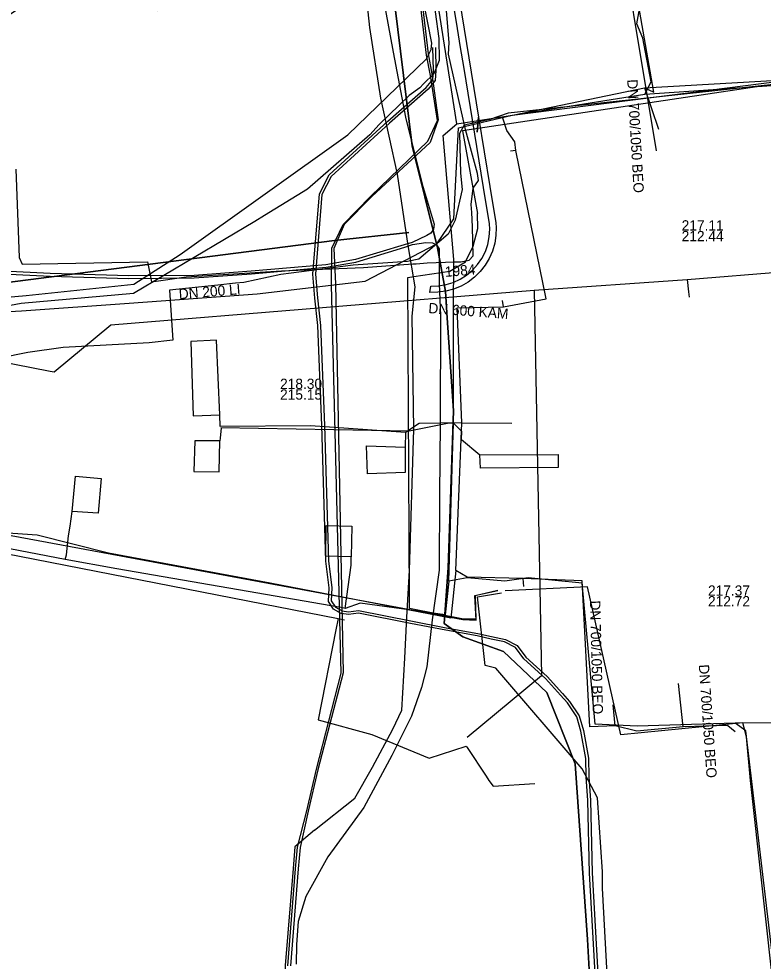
# Model space of a CAD drawing. Extents: x -599951 to -598963, y -1164095 to -1162939.
# Drawn here: x -599282.6 to -599224.6, y -1163195.6 to -1163122.3 of the extents above; entities that cross this region are included whole.
import ezdxf

# ---------------------------------------------------------------- set-up
doc = ezdxf.new("R2010")
doc.units = 0
for name, color, linetype in [('Level 3', 7, 'Continuous'), ('Vrstva 12', 7, 'Continuous'), ('Vrstva 13', 7, 'Continuous'), ('Vrstva 15', 7, 'Continuous'), ('Vrstva 19', 7, 'Continuous'), ('Vrstva 32', 7, 'Continuous'), ('Vrstva 42', 7, 'Continuous'), ('Vrstva 44', 7, 'Continuous'), ('Vrstva 55', 7, 'Continuous'), ('Vrstva 58', 7, 'Continuous')]:
    doc.layers.add(name, color=color, linetype=linetype)

msp = doc.modelspace()

# ---------------------------------------------------------------- linework, layer by layer
at = {"layer": 'Level 3'}
msp.add_lwpolyline([(-599249.571, -1163112.7), (-599246.751, -1163129.952), (-599246.869, -1163131.103), (-599246.751, -1163129.952), (-599245.87, -1163135.341), (-599245.405, -1163138.167), (-599245.38, -1163138.516), (-599245.397, -1163139.141), (-599245.494, -1163139.759), (-599245.669, -1163140.359), (-599245.92, -1163140.933), (-599246.241, -1163141.47), (-599246.628, -1163141.961), (-599247.074, -1163142.399), (-599247.573, -1163142.777), (-599248.116, -1163143.088), (-599248.694, -1163143.327), (-599249.298, -1163143.49), (-599249.917, -1163143.575), (-599250.543, -1163143.581), (-599250.464, -1163143.084), (-599249.872, -1163143.07), (-599249.286, -1163142.976), (-599248.719, -1163142.805), (-599248.18, -1163142.558), (-599247.679, -1163142.241), (-599247.225, -1163141.86), (-599246.827, -1163141.421), (-599246.491, -1163140.933), (-599246.224, -1163140.404), (-599246.03, -1163139.844), (-599245.914, -1163139.262), (-599245.877, -1163138.671), (-599245.901, -1163138.248), (-599245.898, -1163138.248), (-599246.363, -1163135.422), (-599247.904, -1163125.994), (-599248.146, -1163124.512), (-599248.227, -1163124.018), (-599248.389, -1163123.03), (-599250.067, -1163112.766)], dxfattribs=at)
at = {"layer": 'Vrstva 13'}
for p, q in [((-599230.497, -1163142.575), (-599230.399, -1163143.53)), ((-599230.399, -1163143.53), (-599230.35, -1163143.945)), ((-599286.249, -1163148.514), (-599280.123, -1163149.708))]:
    msp.add_line(p, q, dxfattribs=at)
for points in [[(-599280.123, -1163149.708), (-599279.79, -1163149.777), (-599275.388, -1163146.114), (-599242.43, -1163143.42), (-599230.497, -1163142.575), (-599222.86, -1163141.962)], [(-599242.43, -1163143.42), (-599241.851, -1163173.435), (-599247.646, -1163178.245)]]:
    msp.add_lwpolyline(points, dxfattribs=at)
at = {"layer": 'Vrstva 19'}
for points in [[(-599283.03, -1163098.11), (-599283, -1163099.78), (-599282.98, -1163100.28), (-599282.759, -1163104.88), (-599282.75, -1163105.07), (-599281.86, -1163119.78), (-599282.17, -1163121.21), (-599283.38, -1163122.06), (-599284.63, -1163122.58), (-599291.87, -1163126.57), (-599293.2, -1163127.71), (-599294.09, -1163129.72), (-599294.97, -1163134.86), (-599295.61, -1163139.68), (-599296.53, -1163145.79), (-599296.83, -1163147.64), (-599298.55, -1163147.69), (-599298.47, -1163148.23), (-599298.58, -1163159.15), (-599298.84, -1163160.93), (-599298.41, -1163161.06), (-599297.782, -1163161.141), (-599257.68, -1163168.97), (-599257.189, -1163169.066)], [(-599257.68, -1163168.97), (-599257.856, -1163169.853), (-599259.25, -1163176.86), (-599255.07, -1163177.99), (-599250.6, -1163179.85), (-599247.73, -1163178.9), (-599247.64, -1163179.02), (-599246.169, -1163181.239), (-599245.95, -1163181.57), (-599245.61, -1163182.03), (-599242.36, -1163181.82)]]:
    msp.add_lwpolyline(points, dxfattribs=at)
at = {"layer": 'Vrstva 32'}
msp.add_line((-599230.82, -1163177.41), (-599231.188, -1163174.019), dxfattribs=at)
for points in [[(-599233.09, -1163128), (-599234.85, -1163118.03)], [(-599252.44, -1163154.48), (-599259.85, -1163153.98), (-599266.88, -1163154.01), (-599266.91, -1163153.12), (-599267.17, -1163147.3), (-599269.17, -1163147.4), (-599268.97, -1163153.2), (-599266.91, -1163153.12)], [(-599248.05, -1163153.74), (-599251.39, -1163153.8), (-599252.44, -1163154.48), (-599252.46, -1163155.64), (-599252.47, -1163157.61), (-599255.39, -1163157.71), (-599255.47, -1163155.53), (-599252.46, -1163155.64)], [(-599248.51, -1163165.23), (-599248.91, -1163168.93), (-599262.99, -1163166.23), (-599275.57, -1163163.89), (-599281.12, -1163162.48), (-599284.95, -1163162.23), (-599289.25, -1163161.14), (-599288.98, -1163159.59), (-599288.46, -1163154.45), (-599290.46, -1163154.22), (-599290.93, -1163159.09), (-599288.98, -1163159.59)]]:
    msp.add_lwpolyline(points, dxfattribs=at)
at = {"layer": 'Vrstva 42'}
for p, q in [((-599244.136, -1163129.788), (-599217.775, -1163126.435)), ((-599244.136, -1163129.788), (-599217.775, -1163126.435)), ((-599233.82, -1163127.66), (-599232.74, -1163130.88)), ((-599248.304, -1163130.763), (-599244.136, -1163129.788)), ((-599248.304, -1163130.763), (-599244.136, -1163129.788)), ((-599248.665, -1163137.857), (-599248.304, -1163130.763)), ((-599248.665, -1163137.857), (-599248.304, -1163130.763)), ((-599243.86, -1163132.53), (-599244.26, -1163132.58)), ((-599249.995, -1163139.796), (-599248.665, -1163137.857)), ((-599249.995, -1163139.796), (-599248.665, -1163137.857)), ((-599255.591, -1163142.7), (-599249.995, -1163139.796)), ((-599255.591, -1163142.7), (-599249.995, -1163139.796)), ((-599263.99, -1163143.703), (-599255.591, -1163142.7)), ((-599263.99, -1163143.703), (-599255.591, -1163142.7)), ((-599273.951, -1163144.417), (-599263.99, -1163143.703)), ((-599273.951, -1163144.417), (-599263.99, -1163143.703)), ((-599244.8, -1163144.71), (-599244.9, -1163144.2)), ((-599282.345, -1163145.018), (-599273.951, -1163144.417)), ((-599282.345, -1163145.018), (-599273.951, -1163144.417)), ((-599291.448, -1163145.455), (-599282.345, -1163145.018)), ((-599291.448, -1163145.455), (-599282.345, -1163145.018)), ((-599248.05, -1163153.74), (-599244.16, -1163153.77)), ((-599236.11, -1163177.32), (-599236.27, -1163175.68)), ((-599230.82, -1163177.41), (-599230.82, -1163177.41)), ((-599227.33, -1163177.3), (-599226.77, -1163177.77))]:
    msp.add_line(p, q, dxfattribs=at)
for points in [[(-599233.795, -1163128.148), (-599233.302, -1163127.176), (-599233.948, -1163123.785), (-599234.414, -1163122.681), (-599234.221, -1163121.532), (-599236.225, -1163106.079), (-599238.167, -1163087.208), (-599239.204, -1163068.612), (-599240.268, -1163050.177), (-599241.368, -1163030.944), (-599242.272, -1163013.415), (-599243.328, -1162996.385), (-599244.094, -1162980.53), (-599243.642, -1162980.475)], [(-599248.449, -1163130.464), (-599249.959, -1163120.858), (-599250.954, -1163118.557), (-599251.444, -1163116.855), (-599251.095, -1163114.116), (-599252.405, -1163100.665), (-599252.226, -1163100.394)], [(-599236.04, -1163234.14), (-599238.28, -1163193.96), (-599239.23, -1163180.29), (-599241.44, -1163174.74), (-599244.81, -1163171.53), (-599247.98, -1163170.4), (-599249.42, -1163169.35), (-599249.11, -1163165.02), (-599248.71, -1163152.8), (-599249.2, -1163145.57), (-599249.33, -1163143.51), (-599249.96, -1163140.12), (-599251.93, -1163132.17), (-599253.26, -1163121.21), (-599253.403, -1163121.072), (-599253.368, -1163120.491), (-599253.42, -1163117.092), (-599253.131, -1163117.208), (-599252.476, -1163117.031), (-599250.413, -1163117.181), (-599250.237, -1163117.376)], [(-599250.237, -1163117.376), (-599250.413, -1163117.181), (-599252.476, -1163117.031), (-599253.131, -1163117.208), (-599253.42, -1163117.092), (-599253.368, -1163120.491), (-599253.403, -1163121.072), (-599253.26, -1163121.21), (-599251.93, -1163132.17), (-599249.96, -1163140.12), (-599249.33, -1163143.51), (-599249.2, -1163145.57), (-599248.71, -1163152.8), (-599249.11, -1163165.02), (-599249.42, -1163169.35), (-599247.98, -1163170.4), (-599244.81, -1163171.53), (-599241.44, -1163174.74), (-599239.23, -1163180.29), (-599238.28, -1163193.96), (-599236.04, -1163234.14)], [(-599254.35, -1163119.64), (-599253.4, -1163124.88), (-599252.45, -1163129.94), (-599251.14, -1163135.16), (-599250.22, -1163138.26), (-599250.25, -1163138.65), (-599250.47, -1163138.96), (-599250.78, -1163139.16), (-599251.933, -1163139.7), (-599252.539, -1163139.874), (-599256.343, -1163141.023), (-599258.643, -1163141.431), (-599264.458, -1163141.93), (-599268.894, -1163142.26), (-599273.979, -1163142.29), (-599280.106, -1163142.11), (-599283.767, -1163141.931)], [(-599236.04, -1163234.14), (-599238.28, -1163193.96), (-599239.23, -1163180.29), (-599241.44, -1163174.74), (-599244.81, -1163171.53), (-599247.98, -1163170.4), (-599249.42, -1163169.35), (-599249.11, -1163165.02), (-599248.71, -1163152.8), (-599249.2, -1163145.57), (-599249.33, -1163143.51), (-599249.96, -1163140.12), (-599251.93, -1163132.17), (-599253.26, -1163121.21), (-599253.403, -1163121.072), (-599259.906, -1163121.64), (-599271.737, -1163121.65), (-599281.779, -1163121.225), (-599286.734, -1163121.489)], [(-599236.04, -1163234.14), (-599238.28, -1163193.96), (-599239.23, -1163180.29), (-599241.44, -1163174.74), (-599244.81, -1163171.53), (-599247.98, -1163170.4), (-599249.42, -1163169.35), (-599249.11, -1163165.02), (-599248.71, -1163152.8), (-599249.2, -1163145.57), (-599249.33, -1163143.51), (-599249.96, -1163140.12), (-599251.93, -1163132.17), (-599253.26, -1163121.21), (-599253.403, -1163121.072), (-599259.906, -1163121.64), (-599271.737, -1163121.65), (-599281.779, -1163121.225), (-599286.734, -1163121.489)], [(-599236.04, -1163234.14), (-599238.28, -1163193.96), (-599239.23, -1163180.29), (-599241.44, -1163174.74), (-599244.81, -1163171.53), (-599247.98, -1163170.4), (-599249.42, -1163169.35), (-599249.11, -1163165.02), (-599248.71, -1163152.8), (-599249.2, -1163145.57), (-599249.33, -1163143.51), (-599249.96, -1163140.12), (-599251.93, -1163132.17), (-599253.26, -1163121.21)], [(-599236.04, -1163234.14), (-599238.28, -1163193.96), (-599239.23, -1163180.29), (-599241.44, -1163174.74), (-599244.81, -1163171.53), (-599247.98, -1163170.4), (-599249.42, -1163169.35), (-599249.11, -1163165.02), (-599248.71, -1163152.8), (-599249.2, -1163145.57), (-599249.33, -1163143.51), (-599249.96, -1163140.12), (-599251.93, -1163132.17), (-599253.26, -1163121.21)], [(-599236.04, -1163234.14), (-599238.28, -1163193.96), (-599239.23, -1163180.29), (-599241.44, -1163174.74), (-599244.81, -1163171.53), (-599247.98, -1163170.4), (-599249.42, -1163169.35), (-599249.11, -1163165.02), (-599248.71, -1163152.8), (-599249.2, -1163145.57), (-599249.33, -1163143.51), (-599249.96, -1163140.12), (-599251.93, -1163132.17), (-599253.26, -1163121.21)], [(-599203.44, -1163133.2), (-599203.618, -1163130.489), (-599203.79, -1163127.87), (-599203.97, -1163125.9), (-599204.26, -1163125.79), (-599215.12, -1163127.32), (-599216.86, -1163127.37), (-599217.29, -1163126.7), (-599244.45, -1163129.63), (-599245.88, -1163130.11), (-599247.87, -1163130.56), (-599248.24, -1163131.21), (-599248.16, -1163134.29), (-599248.03, -1163135.56), (-599248.57, -1163137.95), (-599249.12, -1163139.05), (-599251.4, -1163141), (-599252.28, -1163141.17), (-599256.52, -1163141.46), (-599262.16, -1163142.19), (-599265.02, -1163142.81), (-599265.67, -1163142.86), (-599267.06, -1163143.01), (-599270.814, -1163143.415)], [(-599244.436, -1163129.83), (-599233.795, -1163128.148), (-599217.451, -1163127.025)], [(-599233.82, -1163127.66), (-599217.52, -1163126.72), (-599217.02, -1163127.48), (-599215.26, -1163127.21)], [(-599243.99, -1163129.75), (-599233.82, -1163127.66), (-599233.09, -1163128)], [(-599248.669, -1163141.017), (-599249.502, -1163131.373), (-599248.449, -1163130.464), (-599244.436, -1163129.83)], [(-599241.49, -1163144.07), (-599243.86, -1163132.53), (-599243.92, -1163131.86), (-599244.55, -1163130.97), (-599244.89, -1163129.95), (-599243.99, -1163129.75)], [(-599252.181, -1163138.924), (-599257.96, -1163139.537), (-599306.724, -1163145.785)], [(-599306.724, -1163145.785), (-599257.96, -1163139.537), (-599252.181, -1163138.924)], [(-599283.813, -1163142.129), (-599280.114, -1163142.31), (-599273.981, -1163142.49), (-599268.886, -1163142.46), (-599264.442, -1163142.13), (-599258.617, -1163141.629), (-599256.297, -1163141.217), (-599252.481, -1163140.066), (-599251.888, -1163139.865), (-599250.85, -1163139.69), (-599250.33, -1163139.72), (-599250.02, -1163139.89), (-599249.83, -1163140.19), (-599249.83, -1163142.92), (-599249.72, -1163145.38), (-599249.74, -1163153.77), (-599249.79, -1163159.33), (-599249.83, -1163165.2), (-599250.36, -1163169.07), (-599250.78, -1163172.73), (-599251.19, -1163174.34), (-599251.97, -1163176.58), (-599253.5, -1163179.64), (-599255.69, -1163183.68), (-599258.49, -1163187.52), (-599260.19, -1163190.6), (-599260.81, -1163192.57), (-599260.93, -1163194.35), (-599260.96, -1163195.88)], [(-599249.066, -1163166.057), (-599248.698, -1163153.749), (-599248.713, -1163144.947), (-599248.669, -1163141.017)], [(-599270.814, -1163143.415), (-599270.57, -1163147.29), (-599272.4, -1163147.52), (-599279.09, -1163147.87), (-599281.84, -1163148.27), (-599286.24, -1163149.13)], [(-599248.43, -1163144.78), (-599244.8, -1163144.71), (-599241.49, -1163144.07)], [(-599248.51, -1163165.23), (-599248.05, -1163153.74), (-599248.43, -1163144.78)], [(-599249.066, -1163166.057), (-599249.356, -1163168.677), (-599255.971, -1163167.763), (-599257.128, -1163168.196), (-599257.477, -1163168.103), (-599274.919, -1163165.108), (-599278.939, -1163164.385), (-599301.203, -1163160.101), (-599327.234, -1163155.124), (-599344.064, -1163151.566)], [(-599248.698, -1163153.749), (-599249.183, -1163153.794), (-599252.154, -1163154.397), (-599266.811, -1163154.136), (-599266.809, -1163154.136)], [(-599248.087, -1163155.038), (-599248.042, -1163154.4), (-599248.698, -1163153.749)], [(-599266.809, -1163154.136), (-599266.88, -1163154.935), (-599266.891, -1163155.14), (-599268.85, -1163155.136), (-599268.922, -1163157.517), (-599266.949, -1163157.556), (-599266.891, -1163155.14)], [(-599248.087, -1163155.038), (-599246.644, -1163156.227), (-599240.551, -1163156.205), (-599240.561, -1163157.223), (-599246.604, -1163157.26), (-599246.644, -1163156.227)], [(-599278.85, -1163164.003), (-599278.688, -1163162.528), (-599278.546, -1163161.775), (-599278.407, -1163160.635), (-599278.132, -1163157.896), (-599276.142, -1163158.073), (-599276.377, -1163160.768), (-599278.407, -1163160.635)], [(-599257.128, -1163168.196), (-599256.662, -1163164.813), (-599256.672, -1163164.356), (-599256.668, -1163164.178), (-599258.652, -1163164.122), (-599258.611, -1163161.728), (-599256.633, -1163161.787), (-599256.668, -1163164.178)], [(-599278.939, -1163164.385), (-599278.85, -1163164.003)], [(-599243.31, -1163165.86), (-599247.65, -1163165.74), (-599248.51, -1163165.23)], [(-599234.397, -1163177.361), (-599237.666, -1163177.208), (-599238.672, -1163166.207), (-599242.885, -1163165.812), (-599244.71, -1163166.072), (-599247.65, -1163165.812), (-599249.066, -1163166.057)], [(-599236.11, -1163177.32), (-599238.08, -1163177.41), (-599238.68, -1163166.04), (-599243.31, -1163165.86), (-599243.26, -1163166.49)], [(-599209.47, -1163180.85), (-599209.865, -1163177.042), (-599226.778, -1163177.129), (-599234.397, -1163177.361)], [(-599221.184, -1163240.787), (-599222.1, -1163221.513), (-599222.943, -1163208.768), (-599223.097, -1163207.287), (-599223.22, -1163204.278), (-599223.353, -1163199.634), (-599225.94, -1163177.72), (-599226.778, -1163177.129)], [(-599227.33, -1163177.3), (-599230.82, -1163177.41), (-599234.43, -1163177.75), (-599236.11, -1163177.32)]]:
    msp.add_lwpolyline(points, dxfattribs=at)
at = {"layer": 'Vrstva 44'}
for points in [[(-599261.6, -1163195.999), (-599261.001, -1163188.45), (-599260.85, -1163186.775), (-599260.117, -1163183.949), (-599259.374, -1163180.702), (-599257.442, -1163173.23), (-599258.199, -1163142.98), (-599258.183, -1163140.143), (-599257.308, -1163138.305), (-599255.136, -1163136.094), (-599250.699, -1163131.803), (-599249.943, -1163130.207), (-599250.496, -1163126.698), (-599250.806, -1163125.125), (-599251.586, -1163118.493), (-599251.863, -1163115.438), (-599253.97, -1163099.588), (-599254.299, -1163095.367), (-599254.889, -1163089.968), (-599258.068, -1163037.789), (-599258.287, -1163035.216), (-599259.111, -1163017.137)], [(-599256.615, -1163034.238), (-599255.051, -1163063.341), (-599255.041, -1163063.97), (-599254.77, -1163067.945), (-599254.74, -1163068.925), (-599253.766, -1163084.009), (-599253.685, -1163084.991), (-599253.231, -1163094.72), (-599253.096, -1163095.753), (-599250.806, -1163116.099), (-599250.73, -1163116.577), (-599250.704, -1163117.25), (-599250.69, -1163117.567), (-599249.852, -1163123.805), (-599249.827, -1163125.526), (-599250.223, -1163126.568), (-599251.042, -1163127.357), (-599251.316, -1163127.662), (-599252.15, -1163128.261), (-599254.504, -1163130.515), (-599255.226, -1163131.307), (-599260.082, -1163135.553), (-599263.428, -1163137.585)], [(-599259.518, -1163185.45), (-599256.398, -1163182.946), (-599255.02, -1163180.54), (-599253.43, -1163177.58), (-599252.72, -1163176.11), (-599252.5, -1163172.06), (-599252.35, -1163168.86), (-599252.13, -1163165.23), (-599251.79, -1163154.24), (-599251.91, -1163145.43), (-599251.69, -1163143.15), (-599252.23, -1163139.94), (-599253.07, -1163134.37), (-599254.37, -1163128.46), (-599255.23, -1163122.95), (-599256.06, -1163115.13), (-599257.1, -1163107.16), (-599257.86, -1163099.64), (-599258.61, -1163091.59), (-599259.1, -1163087.97), (-599260.12, -1163081.16), (-599260.99, -1163074.84), (-599261.54, -1163067.75), (-599262.01, -1163061.43)], [(-599254.721, -1163090.064), (-599254.225, -1163095.427), (-599253.79, -1163099.498), (-599251.728, -1163115.388), (-599251.459, -1163118.412), (-599250.684, -1163125), (-599250.388, -1163126.569), (-599249.886, -1163130.147), (-599250.517, -1163131.902), (-599255.053, -1163136.113), (-599257.218, -1163138.296), (-599258.022, -1163140.172), (-599257.899, -1163142.909), (-599257.286, -1163173.21), (-599259.267, -1163180.76), (-599260.01, -1163183.976), (-599260.651, -1163186.793), (-599260.802, -1163188.467), (-599261.4, -1163196.008)], [(-599263.428, -1163137.585), (-599264.177, -1163138.062), (-599273.629, -1163143.656), (-599282.37, -1163144.448), (-599283.611, -1163144.674), (-599284.37, -1163144.858)], [(-599259.518, -1163185.45), (-599261.049, -1163186.757), (-599261.2, -1163188.433), (-599261.8, -1163195.99), (-599261.852, -1163202.75), (-599260.696, -1163226.16), (-599259.074, -1163253.076), (-599256.803, -1163287.939), (-599256.85, -1163289.18), (-599256.82, -1163289.59)]]:
    msp.add_lwpolyline(points, dxfattribs=at)
at = {"layer": 'Vrstva 55'}
for points in [[(-599247.623, -1162939.4), (-599247.553, -1162942.185), (-599245.906, -1162964.195), (-599244.31, -1162991.72), (-599242.554, -1163019.034), (-599241.44, -1163041.86), (-599240.15, -1163064.23), (-599238.109, -1163088.638), (-599236.478, -1163111.162), (-599232.911, -1163132.565)], [(-599618.855, -1163097.599), (-599597.44, -1163101.87), (-599562.87, -1163108.53), (-599528.51, -1163115.32), (-599493.94, -1163122.04), (-599459.65, -1163128.7), (-599425.29, -1163135.35), (-599390.79, -1163142.01), (-599379.04, -1163144.18), (-599370.08, -1163145.68), (-599333.88, -1163152.87), (-599287.5, -1163161.7), (-599253.07, -1163168.09), (-599247.97, -1163169.04), (-599246.945, -1163169.092), (-599247.03, -1163167.178), (-599245.243, -1163166.795)], [(-599282.79, -1163134), (-599282.52, -1163140.87), (-599282.29, -1163141.38), (-599272.53, -1163141.2), (-599272.21, -1163142.76), (-599269.51, -1163142.36), (-599262.11, -1163141.91), (-599255.71, -1163141.64), (-599251.878, -1163141.37), (-599251.601, -1163141.35), (-599250.75, -1163141.29), (-599248.62, -1163141.21), (-599248.14, -1163141.19), (-599247.48, -1163141.06), (-599247.17, -1163140.73), (-599247.22, -1163138.47), (-599247.28, -1163137.35), (-599247.33, -1163136.75), (-599247.16, -1163135.47), (-599246.75, -1163134.87), (-599246.84, -1163134.33), (-599247.78, -1163130.89), (-599249.09, -1163125.03), (-599249.03, -1163124.12), (-599249.49, -1163118.86)], [(-599216.56, -1163126.31), (-599248, -1163131), (-599246.84, -1163137.44)], [(-599245.243, -1163166.795), (-599247.029, -1163167.204), (-599246.961, -1163169.032), (-599247.918, -1163169.015), (-599252.123, -1163168.195), (-599252.134, -1163167.603), (-599252.25, -1163142.42), (-599251.78, -1163142.35), (-599248.99, -1163141.94), (-599247.77, -1163141.19), (-599247.16, -1163139.97), (-599246.82, -1163138.61), (-599246.84, -1163137.44)], [(-599225.876, -1163178.192), (-599226.166, -1163177.097), (-599235.666, -1163178.032), (-599238.276, -1163166.513), (-599244.675, -1163166.809)], [(-599236.26, -1163205.25), (-599237.11, -1163189.95), (-599237.112, -1163188.692), (-599237.48, -1163182.92), (-599238.68, -1163180.67), (-599245.418, -1163172.838), (-599246.23, -1163172.63), (-599246.84, -1163167.28), (-599244.97, -1163166.97)], [(-599216.968, -1163302.477), (-599218.15, -1163286.65), (-599221.43, -1163231.79), (-599222.71, -1163207.36), (-599225.57, -1163181.59), (-599225.876, -1163178.192)]]:
    msp.add_lwpolyline(points, dxfattribs=at)
at = {"layer": 'Vrstva 58'}
for points in [[(-599250.816, -1163125.405), (-599250.44, -1163124.68), (-599250.38, -1163124.19), (-599251.68, -1163117.57), (-599253.81, -1163096.2), (-599254.72, -1163082.49), (-599255.72, -1163067.96), (-599256.51, -1163056.51), (-599257.77, -1163036.77), (-599259.12, -1163013.85), (-599259.48, -1163006.97), (-599259.9, -1162996.33), (-599262.26, -1162957.4), (-599262.7, -1162943.09), (-599262.952, -1162939.4)], [(-599250.816, -1163125.405), (-599250.44, -1163124.68), (-599250.38, -1163124.19), (-599251.68, -1163117.57), (-599253.81, -1163096.2), (-599254.72, -1163082.49), (-599255.72, -1163067.96), (-599256.51, -1163056.51), (-599257.77, -1163036.77), (-599259.12, -1163013.85), (-599259.48, -1163006.97), (-599259.9, -1162996.33), (-599262.26, -1162957.4), (-599262.7, -1162943.09), (-599262.952, -1162939.4)], [(-599237.13, -1163206.325), (-599237.77, -1163194.776), (-599238.1, -1163188.784), (-599238.24, -1163183.145), (-599238.37, -1163181.294), (-599238.39, -1163179.86), (-599238.787, -1163177.743), (-599239.112, -1163176.623), (-599239.829, -1163175.541), (-599240.365, -1163174.937), (-599241.541, -1163173.631), (-599243.225, -1163172.117), (-599243.867, -1163171.218), (-599244.733, -1163170.785), (-599245.781, -1163170.578), (-599246.85, -1163170.328), (-599249.298, -1163169.888), (-599252.059, -1163169.348), (-599256.103, -1163168.551), (-599256.891, -1163168.661), (-599257.454, -1163168.576), (-599258.041, -1163168.235), (-599258.431, -1163167.638), (-599258.39, -1163166.584), (-599258.65, -1163164.508), (-599258.96, -1163153.953), (-599259.27, -1163146.167), (-599259.5, -1163144.029), (-599259.65, -1163142.17), (-599259.148, -1163135.902), (-599258.381, -1163134.438), (-599253.827, -1163130.245), (-599250.822, -1163127.63), (-599250.318, -1163127.002), (-599250.27, -1163126.298), (-599250.31, -1163124.522)], [(-599250.11, -1163124.518), (-599250.07, -1163126.302), (-599250.122, -1163127.078), (-599250.678, -1163127.77), (-599253.693, -1163130.395), (-599258.219, -1163134.562), (-599258.952, -1163135.958), (-599259.45, -1163142.17), (-599259.3, -1163144.011), (-599259.07, -1163146.153), (-599258.76, -1163153.947), (-599258.45, -1163164.492), (-599258.19, -1163166.576), (-599258.229, -1163167.582), (-599257.899, -1163168.085), (-599257.386, -1163168.384), (-599256.889, -1163168.459), (-599256.097, -1163168.349), (-599252.021, -1163169.152), (-599249.262, -1163169.692), (-599246.81, -1163170.132), (-599245.739, -1163170.382), (-599244.667, -1163170.595), (-599243.733, -1163171.062), (-599243.075, -1163171.983), (-599241.399, -1163173.489), (-599240.215, -1163174.803), (-599239.671, -1163175.419), (-599238.928, -1163176.537), (-599238.593, -1163177.697), (-599238.19, -1163179.84), (-599238.17, -1163181.286), (-599238.04, -1163183.135), (-599237.9, -1163188.776), (-599237.57, -1163194.765), (-599236.93, -1163206.315)], [(-599467.296, -1163128.595), (-599449.626, -1163131.895), (-599436.436, -1163134.445), (-599424.726, -1163136.395), (-599396.496, -1163142.065), (-599373.566, -1163146.345), (-599347.266, -1163151.545), (-599320.246, -1163156.535), (-599305.966, -1163159.545), (-599305.336, -1163159.455), (-599304.796, -1163158.485), (-599303.026, -1163148.025), (-599302.836, -1163147.375), (-599302.096, -1163144.325), (-599301.866, -1163144.085), (-599301.526, -1163143.995), (-599292.886, -1163144.775), (-599281.976, -1163143.815), (-599273.586, -1163142.935), (-599269.986, -1163140.635), (-599256.936, -1163131.305), (-599250.816, -1163125.405)], [(-599467.296, -1163128.595), (-599449.626, -1163131.895), (-599436.436, -1163134.445), (-599424.726, -1163136.395), (-599396.496, -1163142.065), (-599373.566, -1163146.345), (-599347.266, -1163151.545), (-599320.246, -1163156.535), (-599305.966, -1163159.545), (-599305.336, -1163159.455), (-599304.796, -1163158.485), (-599303.026, -1163148.025), (-599302.836, -1163147.375), (-599302.096, -1163144.325), (-599301.866, -1163144.085), (-599301.526, -1163143.995), (-599292.886, -1163144.775), (-599281.976, -1163143.815), (-599273.586, -1163142.935), (-599269.986, -1163140.635), (-599256.936, -1163131.305), (-599250.816, -1163125.405)]]:
    msp.add_lwpolyline(points, dxfattribs=at)

# ---------------------------------------------------------------- texts
at = {"layer": 'Vrstva 12'}
for s, rotation, p in [('DN 700/1050 BEO', 273.32311, (-599235.18, -1163127.014)), ('DN 600 KAM', 355.74418, (-599250.682, -1163145.186)), ('DN 700/1050 BEO', 271.45373, (-599238.078, -1163167.573)), ('DN 700/1050 BEO', 273.98982, (-599229.606, -1163172.57))]:
    msp.add_text(s, height=0.8, rotation=rotation, dxfattribs=at).set_placement(p)
for s, p in [('217.11', (-599230.936, -1163138.765)), ('212.44', (-599230.936, -1163139.597)), ('218.30', (-599262.21, -1163151.098)), ('215.15', (-599262.21, -1163151.93)), ('217.37', (-599228.887, -1163167.192)), ('212.72', (-599228.887, -1163168.024))]:
    msp.add_text(s, height=0.8, dxfattribs=at).set_placement(p)
at = {"layer": 'Vrstva 15'}
for s, p in [('1984', (-599249.341, -1163142.38)), ('DN 200 LI', (-599270.066, -1163144.114))]:
    msp.add_text(s, height=0.8, rotation=4.69825, dxfattribs=at).set_placement(p)

doc.saveas('drawing.dxf')
